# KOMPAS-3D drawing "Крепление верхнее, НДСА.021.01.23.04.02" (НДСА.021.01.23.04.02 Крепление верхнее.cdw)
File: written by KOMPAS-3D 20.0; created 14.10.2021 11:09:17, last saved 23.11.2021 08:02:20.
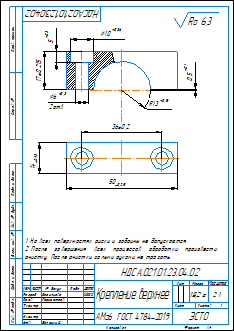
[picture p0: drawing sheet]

Sheet 1: A4, portrait

Document properties: Полное имя файла: C:\Users\s.pischagina\Desktop\PLM\НДСА.021.01.23.04.02 Крепление верхнее.cdw; Автор: adminzsc; Параметр неуказанной шероховатости: Ra 6,3; PLM_CDWXDTO: <item xmlns="http://appius.ru/pdm" xmlns:xs="http://www.w3.org/2001/XMLSchema" xmlns:xsi="http://www.w3.org/2001/XMLSchema-instance" xsi:type="item">  <element xmlns:d2p1="http://v8.1c.ru/8.1/data/enterprise/current-config" xsi:type="d2p1:CatalogRef.aps_Элемен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; Масса: 0.0182029; PDM_DOCXDTO: <item xmlns="http://appius.ru/pdm" xmlns:xs="http://www.w3.org/2001/XMLSchema" xmlns:xsi="http://www.w3.org/2001/XMLSchema-instance" xsi:type="item">  <element xmlns:d2p1="http://v8.1c.ru/8.1/data/enterprise/current-config" xsi:type="d2p1:CatalogRef.aps_Элемен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; PDM_ITEMXDTO: <item xmlns="http://appius.ru/pdm" xmlns:xs="http://www.w3.org/2001/XMLSchema" xmlns:xsi="http://www.w3.org/2001/XMLSchema-instance" xsi:type="item">  <element xmlns:d2p1="http://v8.1c.ru/8.1/data/enterprise/current-config" xsi:type="d2p1:CatalogRef.aps_Элемен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; PDM_DRAWINGXDTO: <item xmlns="http://appius.ru/pdm" xmlns:xs="http://www.w3.org/2001/XMLSchema" xmlns:xsi="http://www.w3.org/2001/XMLSchema-instance" xsi:type="item">  <element xmlns:d2p1="http://v8.1c.ru/8.1/data/enterprise/current-config" xsi:type="d2p1:CatalogRef.aps_Элемен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

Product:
- Part/product: Крепление верхнее  | designation НДСА.021.01.23.04.02
    Материал: АМг6  ГОСТ 4784-2019 (density 2640 kg/m3)
    Масса: 0.0182029
    additional columns: <item xmlns="http://appius.ru/pdm" xmlns:xs="http://www.w3.org/2001/XMLSchema" x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; <item xmlns="http://appius.ru/pdm" xmlns:xs="http://www.w3.org/2001/XMLSchema" x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; <item xmlns="http://appius.ru/pdm" xmlns:xs="http://www.w3.org/2001/XMLSchema" x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
    source file: НДСА.002.01.05.02.00 Крепление верхнее.cdw, НДСА.021.01.23.04.02 Крепление верхнее.cdw

Title block, sheet 1: Наименование: Крепление верхнее; designation: НДСА.021.01.23.04.02; Материал: АМг6  ГОСТ 4784-2019; Масса: 18,2 г; Количество листов документа: 1; organisation: ЭСТО; Форматы листов документа: A4; stored path: C:\Users\vasilyeva\Desktop\PM_APPIUS\НДСА.002.01.05.02.00 Крепление верхнее.cdw; Разработал: Васильева; Проверил: Горностаев; Утвердил: Белецкий; Разработал, date: 14.10.2021

Views: Вид 1, Местный разрез 1, Спереди, Проекционный вид 3
Referenced files in C:\Users\s.pischagina\Desktop\PLM\: НДСА.021.01.23.04.02 Крепление верхнее.m3d
Referenced files in C:\Users\vasilyeva\Desktop\PM_APPIUS\: НДСА.002.01.05.02.00 Крепление верхнее 25.m3d, НДСА.021.01.23.04.02 Крепление верхнее.m3d
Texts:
  Ra 6,3
  НДСА.021.01.23.04.02 Крепление верхнее
Dimensions and other numbers on the sheet: 17±0,215; 13; 0,5; 10; 5; 6; 2отв; 14; 50; 36±0,2; 2:1; 1; 18,2 г; 14.10.2021

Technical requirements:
  На всех поверхностях риски и забоины не допускаются.
  После завершения всех процессов обработки произвести
  очистку. После очистки голыми руками не трогать.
